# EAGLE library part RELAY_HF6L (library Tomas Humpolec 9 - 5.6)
HF6 Relay types: Latching 1 coil High performance shielded high frequency relay switch for 50 Ohm systems, 1 pole, polarized coil Surface Mount Technology (SMT) ROHS compliant (Directive 2002/95/EC) all date codes. Features - Y-Design - Frequency range DC to 6 GHz - Impendance 50 ? - Small dimensions (16 mm x 7.6 mm x 10 mm) - 1 change over contact (1 form C / SPDT) - Immersion cleanable - Low power consumption (?140 mW) Typical applications - Measurement and test equipment ATE - Wireless base stations and antennas - Wireless Infrastructure - RF power amplifier AXICOM Tyco Electronics EC Trutnov s.r.o. Komenského 821 CZ-541 01 Trutnov / Czech Republic E-mail: axicom@tycoelectronics.com
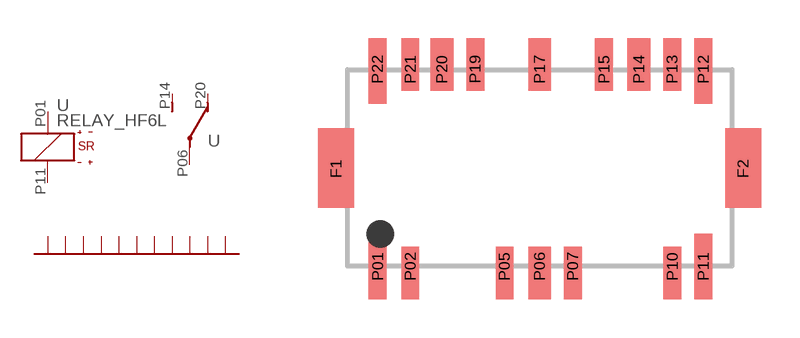
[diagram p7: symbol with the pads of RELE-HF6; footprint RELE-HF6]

Designator prefix -; gates G$1=RE-CIVKARS G$2=RE-KONT1P G$3=GND G$4=GND G$5=GND G$6=GND G$7=GND G$8=GND G$9=GND G$10=GND G$11=GND G$12=GND G$13=GND

## RELAY_HF6L_LATH  [RELE-HF6]
P01  G$1:+  pas
P02  G$3:GND  sup
P05  G$4:GND  sup
P06  G$2:CO  pas
P07  G$5:GND  sup
P10  G$6:GND  sup
P11  G$1:-  pas
P12  G$7:GND  sup
P13  G$8:GND  sup
P14  G$2:NO  pas
P15  G$9:GND  sup
P17  G$10:GND  sup
P19  G$11:GND  sup
P20  G$2:NC  pas
P21  G$12:GND  sup
P22  G$13:GND  sup

## Footprint RELE-HF6 (pad centres in mm)
smd 0.635 x 1.27: F1 -8.065,-1.27; F2 7.811,-1.27; P01 -6.439,-5.08; P02 -5.169,-5.08; P05 -1.499,-5.08; P06 -0.127,-5.08; P07 1.168,-5.08; P10 5.055,-5.08; P11 6.261,-5.08; P12 6.261,2.603; P13 5.042,2.603; P14 3.747,2.603; P15 2.388,2.603; P17 -0.127,2.603; P19 -2.642,2.616; P20 -3.937,2.603; P21 -5.169,2.603; P22 -6.452,2.603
